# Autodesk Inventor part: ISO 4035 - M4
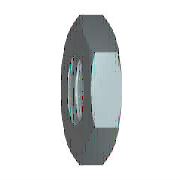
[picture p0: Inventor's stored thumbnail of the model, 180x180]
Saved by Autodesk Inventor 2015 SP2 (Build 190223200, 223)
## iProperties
IsCustomPart: 0
Created: 2012-02
Part Number: ISO 4035 - M4
Material: Edelstahl, 440C
Description: Sechskantmuttern, niedrige Form (mit Fase) - Produktklasse A und B
Document SubType Name: Modeling
Standard: ISO 4035
Designer: SteffenHaase
Standard Revision: Third edition 1999-08-15
Standards Organization: ISO
Language: de-DE
Size Designation: M4
Categories: <MemberInstance><Categories><Category DisplayName="Verbindungselemente" InternalName="e4da775c-781d-43d5-af7c-5136215cf5a6" Mnemonic="FSTN"><Category DisplayNam
Density: 7.75 g/cm^3
Appearance: Halbpoliert
Author: SteffenHaase
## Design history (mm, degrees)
sketch "Skizze1"
  geometry: L1 (-4.041, 0)-(-2.021, 3.5); L2 (-2.021, 3.5)-(2.021, 3.5); L3 (2.021, 3.5)-(4.041, 0); L4 (4.041, 0)-(2.021, -3.5); L5 (2.021, -3.5)-(-2.021, -3.5); L6 (-2.021, -3.5)-(-4.041, 0); 2 further points
  constraints: 12 end point, 1 coincident, 1 horizontal, 11 other
  dimensions: "d0" = 8.0829 distance of L3.end L1.start (= 1.1547 x SW)
extrude "Körper" new body sketch "Skizze1" distance "d1" = 2.2 (= KOH); taper "d2" = 0 deg
sketch "Skizze2"
  geometry: L1 (0, 2.021)-(0, 4.041) reference; L2 (0, 4.041)-(2.2, 4.041) reference; L3 (2.2, 2.021)-(2.2, 4.041) reference; L4 (-0.44, 0)-(2.64, 0) reference; L5 (0.63, 4.041)-(0, 2.95); L6 (1.57, 4.041)-(2.2, 2.95)
  constraints: 4 end point, 4 point on line
  dimensions: "d3" = 30 deg angle of L1 L5 (= ANG1); "d4" = 30 deg angle of L3 L6 (= ANG2); "d5" = 5.9 diameter of L5.end L4 (= SW0); "d6" = 5.9 diameter of L6.end L4 (= SW01)
revolve "Fase1" sketch "Skizze2" stored, may be unused: angle "d7" = 90 deg
sketch "Skizze3"
  geometry: 4 further points
  constraints: 1 coincident, 1 other
hole "Gewinde" sketch "Skizze3" at (0, 0) diameter "d25" = 3.242; stored, may be unused: countersink angle "d29" = 82 deg, drill point angle "d31" = 118 deg; dims "d26" = 6, "d27" = 4, "d28" = 2, "d30" = 8
workaxis "Work Axis1"
workplane "Work Plane1"
body "Solid1"
chamfer "Fase2" distance "d8" = 0.37889 (= -0.5 x GD1 + 0.5 x NND); stored, may be unused: angle "d9" = 30 deg, second distance "d40" = 0.37889 (= -0.5 x GD1 + 0.5 x NND)
chamfer "Fase3" distance "d10" = 0.37889 (= -0.5 x GD1 + 0.5 x NND); stored, may be unused: angle "d11" = 30 deg, second distance "d41" = 0.37889 (= -0.5 x GD1 + 0.5 x NND)
other parameters: "ANG1" = 30 deg [user parameter; used in 1 equation term], "ANG2" = 30 deg [user parameter; used in 1 equation term], "NND" = 4 [user parameter; used in 4 equation terms], "KOH" = 2.2 [user parameter; used in 1 equation term], "SW" = 7 [user parameter; used in 2 equation terms], "SW0" = 5.9 [user parameter; used in 2 equation terms], "SW01" = 5.9 (= SW0) [user parameter; used in 1 equation term], "GD1" = 3.24223 (computed from THREADDIA, PTC, TOA) [user parameter; used in 4 equation terms], "d13" = 0, "d14" = 0, "d39" = 0, "d42" = 0, "GUL" = 0.37889 (= 0.541266 x PTC) [user parameter], "TPU" = 14.28571 (computed from PTC) [user parameter], "THREADDIA" = 4 [user parameter; used in 1 equation term], "TOA" = 30 deg [user parameter; used in 1 equation term], "PTC" = 0.7 [user parameter; used in 4 equation terms], "E0" = 8.085 (= 1.155 x SW) [user parameter], "GAL" = 0.37889 (= 0.541266 x PTC) [user parameter]
